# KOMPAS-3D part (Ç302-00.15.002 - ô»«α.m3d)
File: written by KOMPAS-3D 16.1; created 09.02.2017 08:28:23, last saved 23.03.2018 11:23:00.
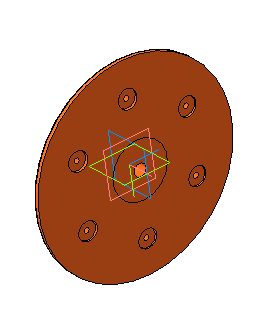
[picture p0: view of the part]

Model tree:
1. Эскиз:7
2. Операция вращения:1
     Угол 1 = 360
3. Скругление:18
     Радиус = 6
4. Скругление:19
     Радиус = 2
5. Эскиз:20
6. Вырезать элемент выдавливания:1
     Расстояние 2 = 20; Расстояние 1 = 15
7. Эскиз:21
8. Вырезать элемент выдавливания:2
     Расстояние 1 = 5.5
9. Массив по концентрической сетке:1  (with: Вырезать элемент выдавливания:1, Эскиз:20, Вырезать элемент выдавливания:2, Эскиз:21)  (labels: Полиамид П-12Б-20  ТУ 6-05-898-73)  (6 pattern instances)
     Геометрический массив = 5; Шаг 2 = 360

Expressions: 250/2; (250-60)/2; (250-60)/2+12; 13.5/2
